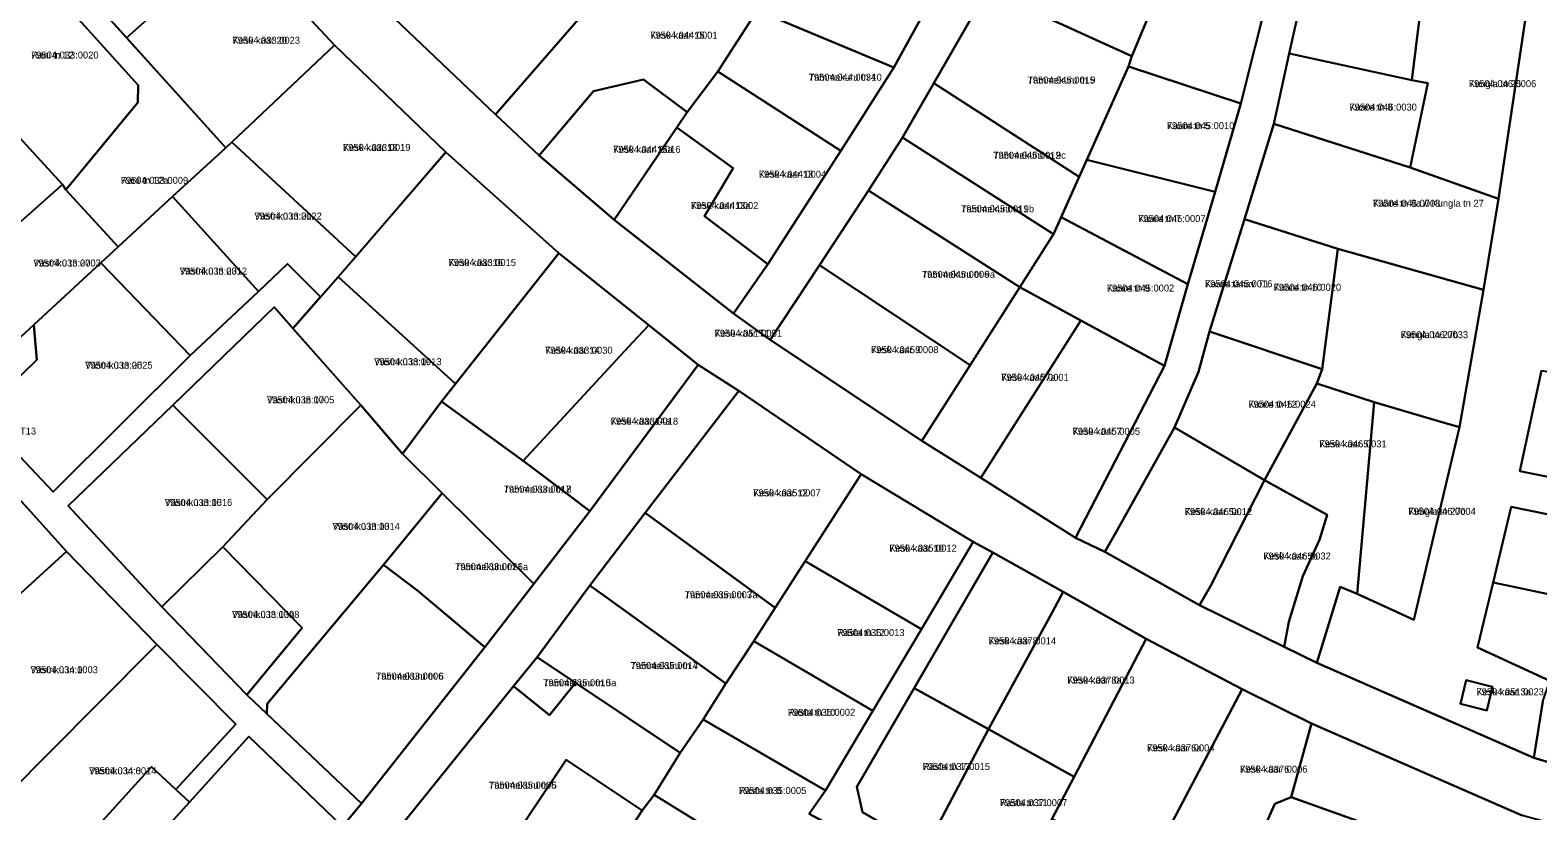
# Model space of a CAD drawing. Extents: x 643847 to 663718, y 6468443 to 6482775.
# Drawn here: x 658477 to 658801.3, y 6472072.8 to 6472240.8 of the extents above; entities that cross this region are included whole.
import ezdxf

# ---------------------------------------------------------------- set-up
doc = ezdxf.new("R2010")
doc.units = 0
for name, color, linetype in [('L_AADRESS', 7, 'Continuous'), ('PIIR', 7, 'Continuous'), ('TUNNUS', 7, 'Continuous')]:
    doc.layers.add(name, color=color, linetype=linetype)

msp = doc.modelspace()

# ---------------------------------------------------------------- linework, layer by layer
at = {"layer": 'PIIR'}
for points in [[(658501.31, 6472282.78), (658521.37, 6472260.27), (658497.7, 6472239.15), (658477.51, 6472261.56)], [(658674.31, 6472253.79), (658662.74, 6472232.74), (658633.36, 6472245.03), (658646.68, 6472277.15), (658679.34, 6472264.45)], [(658553.88, 6472244.64), (658578.06, 6472272.69), (658601.23, 6472250.52), (658577.08, 6472222.66)], [(658691.93, 6472269.29), (658723.96, 6472259.97), (658722.5, 6472256.13), (658721.04, 6472252.31), (658713.91, 6472235.24), (658682.82, 6472249.43)], [(658577.08, 6472222.66), (658601.23, 6472250.52), (658613.02, 6472264.12), (658615.23, 6472261.95), (658617.74, 6472260.17), (658633.36, 6472245.03), (658624.87, 6472231.88), (658618.28, 6472223.16), (658608.9, 6472230.22), (658598.11, 6472227.64), (658586.42, 6472213.82)], [(658477.51, 6472261.56), (658495.65, 6472241.43), (658519.04, 6472215.49), (658507.6, 6472204.98), (658495.9, 6472194.17), (658484.64, 6472206.47), (658500.11, 6472225.22), (658500.19, 6472228.97), (658473.85, 6472258.16)], [(658542.42, 6472237.59), (658520.34, 6472216.73), (658519.04, 6472215.49), (658497.7, 6472239.15), (658521.37, 6472260.27)], [(658473.85, 6472258.16), (658500.19, 6472228.97), (658500.11, 6472225.22), (658484.64, 6472206.47), (658483.9, 6472207.58), (658454.15, 6472239.98)], [(658737.36, 6472225.01), (658713.24, 6472232.98), (658713.91, 6472235.24), (658721.04, 6472252.31), (658722.5, 6472256.13), (658743.33, 6472248.77)], [(658752.03, 6472254.71), (658776.81, 6472251.57), (658774.16, 6472230.07), (658747.8, 6472235.78)], [(658682.82, 6472249.43), (658713.91, 6472235.24), (658713.24, 6472232.98), (658704.23, 6472212.87), (658702.59, 6472209.21), (658671.32, 6472229.38)], [(658773.82, 6472211.22), (658777.6, 6472229.42), (658774.16, 6472230.07), (658776.81, 6472251.57), (658799.04, 6472248.64), (658798.58, 6472243.38), (658792.84, 6472204.51)], [(658633.36, 6472245.03), (658662.74, 6472232.74), (658651.33, 6472214.81), (658624.87, 6472231.88)], [(658454.04, 6472189.46), (658430.48, 6472218.38), (658454.15, 6472239.98), (658483.9, 6472207.58), (658460.17, 6472186.56)], [(658566.41, 6472214.54), (658547, 6472192.05), (658520.34, 6472216.73), (658542.42, 6472237.59)], [(658747.8, 6472235.78), (658774.16, 6472230.07), (658777.6, 6472229.42), (658773.82, 6472211.22), (658744.49, 6472220.66)], [(658731.83, 6472206.01), (658704.23, 6472212.87), (658713.24, 6472232.98), (658737.36, 6472225.01)], [(658586.42, 6472213.82), (658598.11, 6472227.64), (658608.9, 6472230.22), (658618.28, 6472223.16), (658616.05, 6472219.84), (658602.56, 6472199.98)], [(658635.63, 6472190.46), (658622.05, 6472200.8), (658628.21, 6472211.12), (658616.05, 6472219.84), (658618.28, 6472223.16), (658624.87, 6472231.88), (658651.33, 6472214.81)], [(658671.32, 6472229.38), (658702.59, 6472209.21), (658698.72, 6472200.54), (658697.08, 6472196.89), (658664.62, 6472217.69)], [(658602.56, 6472199.98), (658616.05, 6472219.84), (658628.21, 6472211.12), (658622.05, 6472200.8), (658635.63, 6472190.46), (658628.28, 6472179.79)], [(658744.49, 6472220.66), (658773.82, 6472211.22), (658792.84, 6472204.51), (658789.58, 6472184.94), (658758.26, 6472193.72), (658738.2, 6472200.11)], [(658532.31, 6472190.51), (658526.1, 6472184.58), (658507.6, 6472204.98), (658519.04, 6472215.49), (658520.34, 6472216.73), (658547, 6472192.05), (658543.24, 6472187.7), (658539.44, 6472183.38)], [(658664.62, 6472217.69), (658697.08, 6472196.89), (658689.83, 6472185.51), (658657.3, 6472206.3)], [(658590.68, 6472192.79), (658568.44, 6472164.71), (658543.24, 6472187.7), (658566.41, 6472214.54)], [(658725.96, 6472186.14), (658698.72, 6472200.54), (658702.59, 6472209.21), (658704.23, 6472212.87), (658731.83, 6472206.01)], [(658492.15, 6472190.71), (658477.72, 6472177.39), (658472.22, 6472172.3), (658460.17, 6472186.56), (658483.9, 6472207.58), (658484.64, 6472206.47), (658495.9, 6472194.17)], [(658511.35, 6472170.82), (658492.15, 6472190.71), (658495.9, 6472194.17), (658507.6, 6472204.98), (658526.1, 6472184.58)], [(658657.3, 6472206.3), (658689.83, 6472185.51), (658679.13, 6472168.7), (658646.77, 6472190.2)], [(658720.94, 6472168.56), (658702.98, 6472178.34), (658689.83, 6472185.51), (658697.08, 6472196.89), (658698.72, 6472200.54), (658725.96, 6472186.14)], [(658738.2, 6472200.11), (658758.26, 6472193.72), (658754.9, 6472167.83), (658730.65, 6472175.96)], [(658784.45, 6472155.33), (658779.65, 6472156.74), (658766.03, 6472160.72), (658753.73, 6472164.79), (658754.9, 6472167.83), (658758.26, 6472193.72), (658789.58, 6472184.94)], [(658466.22, 6472157.98), (658478.38, 6472169.82), (658477.72, 6472177.39), (658492.15, 6472190.71), (658511.35, 6472170.82), (658481.91, 6472141.41)], [(658590.68, 6472192.79), (658610.02, 6472177.32), (658606.63, 6472173.64), (658583.01, 6472148.14), (658565.46, 6472160.9), (658568.44, 6472164.71)], [(658543.24, 6472187.7), (658568.44, 6472164.71), (658565.46, 6472160.9), (658557.06, 6472149.62), (658548.1, 6472160.09), (658533.49, 6472176.63)], [(658646.77, 6472190.2), (658679.13, 6472168.7), (658668.75, 6472152.39), (658636.16, 6472174.16)], [(658668.75, 6472152.39), (658679.13, 6472168.7), (658689.83, 6472185.51), (658702.98, 6472178.34), (658681.44, 6472144.43)], [(658529.48, 6472181.17), (658548.1, 6472160.09), (658527.94, 6472139.8), (658507.62, 6472160.1)], [(658620.68, 6472168.8), (658597.38, 6472137.31), (658593.39, 6472140.32), (658583.01, 6472148.14), (658606.63, 6472173.64), (658610.02, 6472177.32)], [(658681.44, 6472144.43), (658702.98, 6472178.34), (658720.94, 6472168.56), (658701.84, 6472131.51)], [(658728.29, 6472167.28), (658730.65, 6472175.96), (658754.9, 6472167.83), (658753.73, 6472164.79), (658742.46, 6472143.92), (658723.12, 6472155.28)], [(658486.97, 6471987.22), (658470.14, 6471967.41), (658462.76, 6471973.64), (658481.78, 6471995.53), (658502.37, 6472019.24), (658520.73, 6472040.77), (658544.18, 6472069.39), (658548.25, 6472074.35), (658574.77, 6472108.01), (658585.28, 6472121.63), (658597.38, 6472137.31), (658620.68, 6472168.8), (658629.38, 6472163.16), (658609.28, 6472136.89), (658597.33, 6472121.3), (658586.04, 6472105.83), (658580.96, 6472099.65), (658555.3, 6472067.81), (658551.14, 6472062.72), (658529, 6472036.46), (658513.76, 6472018.4), (658509.71, 6472013.53)], [(658802.08, 6472167.57), (658837.99, 6472160.95), (658835.29, 6472143.37), (658834.56, 6472138.45), (658797.4, 6472145.92)], [(658746.72, 6472108.09), (658747.7, 6472113.44), (658750.72, 6472123.27), (658754.32, 6472131.14), (658755.93, 6472136.48), (658742.46, 6472143.92), (658753.73, 6472164.79), (658766.03, 6472160.72), (658762.37, 6472119.49), (658758.74, 6472120.97), (658755.74, 6472111.16), (658753.71, 6472104.63)], [(658655.71, 6472145.26), (658643.66, 6472126.52), (658637.19, 6472116.45), (658609.28, 6472136.89), (658629.38, 6472163.16)], [(658527.94, 6472139.8), (658518.41, 6472129.58), (658505.27, 6472116.72), (658485.17, 6472138.46), (658507.62, 6472160.1)], [(658523.57, 6472097.77), (658535.49, 6472112.17), (658518.41, 6472129.58), (658527.94, 6472139.8), (658548.1, 6472160.09), (658557.06, 6472149.62), (658565.58, 6472141.17), (658552.94, 6472125.71), (658527.97, 6472095.81), (658527.89, 6472093.66)], [(658585.28, 6472121.63), (658565.58, 6472141.17), (658557.06, 6472149.62), (658565.46, 6472160.9), (658583.01, 6472148.14), (658593.39, 6472140.32), (658597.38, 6472137.31)], [(658774.61, 6472113.89), (658770.07, 6472115.97), (658762.37, 6472119.49), (658766.03, 6472160.72), (658779.65, 6472156.74), (658784.45, 6472155.33)], [(658708.16, 6472128.51), (658710.69, 6472133.05), (658723.12, 6472155.28), (658742.46, 6472143.92), (658730.95, 6472121.26), (658728.52, 6472117.08)], [(658451.55, 6472144.62), (658455.66, 6472140.04), (658466.05, 6472149.31), (658484.75, 6472128.6), (658455.79, 6472102.23), (658433.63, 6472128.35)], [(658679.82, 6472130.67), (658668.68, 6472111.88), (658643.66, 6472126.52), (658655.71, 6472145.26)], [(658728.52, 6472117.08), (658730.95, 6472121.26), (658742.46, 6472143.92), (658755.93, 6472136.48), (658754.32, 6472131.14), (658750.72, 6472123.27), (658747.7, 6472113.44), (658746.72, 6472108.09)], [(658574.77, 6472108.01), (658560.33, 6472120.14), (658552.94, 6472125.71), (658565.58, 6472141.17), (658585.28, 6472121.63)], [(658609.28, 6472136.89), (658637.19, 6472116.45), (658632.6, 6472109.31), (658626.6, 6472100.21), (658601.39, 6472118.38), (658597.33, 6472121.3)], [(658795.56, 6472138.2), (658833.2, 6472130.55), (658832.6, 6472126.98), (658830.37, 6472113.72), (658791.67, 6472121.95)], [(658505.27, 6472116.72), (658518.41, 6472129.58), (658535.49, 6472112.17), (658523.57, 6472097.77)], [(658670.36, 6472019.49), (658658.46, 6471997.89), (658653.44, 6472001.73), (658672.58, 6472036.92), (658678.34, 6472047.5), (658676.34, 6472053.77), (658649.48, 6472069.46), (658644.52, 6472072.15), (658648.05, 6472077.18), (658658.22, 6472094.28), (658668.68, 6472111.88), (658679.82, 6472130.67), (658684.01, 6472128.39), (658667.09, 6472099.2), (658654.75, 6472077.92), (658656.02, 6472072.5), (658669.53, 6472064.64), (658681.97, 6472057.51), (658691.21, 6472060.31), (658688.96, 6472054.5), (658679.74, 6472037.54)], [(658487.19, 6472126.08), (658504.19, 6472108.57), (658491.16, 6472095.44), (658472.1, 6472076.22), (658452.09, 6472098.87), (658455.79, 6472102.23), (658484.75, 6472128.6)], [(658548.25, 6472074.35), (658527.89, 6472093.66), (658527.97, 6472095.81), (658552.94, 6472125.71), (658560.33, 6472120.14), (658574.77, 6472108.01)], [(658658.22, 6472094.28), (658632.6, 6472109.31), (658637.19, 6472116.45), (658643.66, 6472126.52), (658668.68, 6472111.88)], [(658684.01, 6472128.39), (658699.19, 6472119.89), (658696.8, 6472115.5), (658683.12, 6472090.34), (658667.09, 6472099.2)], [(658597.33, 6472121.3), (658601.39, 6472118.38), (658626.6, 6472100.21), (658621.75, 6472092.42), (658616.79, 6472085.28), (658594.25, 6472100.36), (658586.04, 6472105.83)], [(658716.99, 6472109.8), (658701.56, 6472080.14), (658683.12, 6472090.34), (658696.8, 6472115.5), (658699.19, 6472119.89)], [(658853.88, 6472071.07), (658834.71, 6472075.16), (658815.16, 6472079.85), (658800.44, 6472084.23), (658802.33, 6472096.34), (658803.83, 6472100.78), (658788.31, 6472107.93), (658791.67, 6472121.95), (658830.37, 6472113.72), (658827.65, 6472097.48), (658846.62, 6472093.3), (658856.41, 6472091.14), (658865.05, 6472090.8), (658861.31, 6472069.89)], [(658648.05, 6472077.18), (658621.75, 6472092.42), (658626.6, 6472100.21), (658632.6, 6472109.31), (658658.22, 6472094.28)], [(658737.66, 6472098.99), (658721.87, 6472068.98), (658718.03, 6472061.11), (658696.76, 6472071.01), (658701.56, 6472080.14), (658716.99, 6472109.8)], [(658521.24, 6472091.45), (658508.32, 6472077.4), (658503.09, 6472082.27), (658472.25, 6472048.25), (658458.02, 6472062.02), (658472.1, 6472076.22), (658491.16, 6472095.44), (658504.19, 6472108.57)], [(658586.04, 6472105.83), (658594.25, 6472100.36), (658588.71, 6472093.38), (658580.96, 6472099.65)], [(658580.96, 6472099.65), (658588.71, 6472093.38), (658594.25, 6472100.36), (658616.79, 6472085.28), (658611.19, 6472076.22), (658608.6, 6472072.86), (658592.28, 6472083.8), (658575.79, 6472059.09), (658572.96, 6472054.74), (658555.3, 6472067.81)], [(658784.65, 6472095.85), (658785.86, 6472100.93), (658791.49, 6472099.44), (658790.28, 6472094.36)], [(658790.28, 6472094.36), (658791.49, 6472099.44), (658785.86, 6472100.93), (658784.65, 6472095.85)], [(658667.09, 6472099.2), (658683.12, 6472090.34), (658669.53, 6472064.64), (658656.02, 6472072.5), (658654.75, 6472077.92)], [(658752.56, 6472091.57), (658748.23, 6472075.76), (658744.7, 6472074.32), (658739.68, 6472063.05), (658721.87, 6472068.98), (658737.66, 6472098.99)], [(658649.48, 6472069.46), (658643.98, 6472060.39), (658627.69, 6472070.13), (658625.82, 6472067.19), (658611.19, 6472076.22), (658616.79, 6472085.28), (658621.75, 6472092.42), (658648.05, 6472077.18), (658644.52, 6472072.15)], [(658683.12, 6472090.34), (658701.56, 6472080.14), (658696.76, 6472071.01), (658691.21, 6472060.31), (658681.97, 6472057.51), (658669.53, 6472064.64)], [(658520.73, 6472040.77), (658497.89, 6472059.97), (658511.24, 6472074.68), (658524.02, 6472088.79), (658544.18, 6472069.39)], [(658589.6, 6472043.55), (658572.96, 6472054.74), (658575.79, 6472059.09), (658592.28, 6472083.8), (658608.6, 6472072.86), (658592.28, 6472047.69)], [(658497.89, 6472059.97), (658480.25, 6472040.51), (658472.25, 6472048.25), (658503.09, 6472082.27), (658508.32, 6472077.4), (658511.24, 6472074.68)], [(658589.6, 6472043.55), (658592.28, 6472047.69), (658608.6, 6472072.86), (658611.19, 6472076.22), (658625.82, 6472067.19), (658604.12, 6472033.8)], [(658753.94, 6472045.33), (658718.7, 6472060.93), (658718.03, 6472061.11), (658721.87, 6472068.98), (658739.68, 6472063.05), (658744.7, 6472074.32), (658748.23, 6472075.76), (658762.23, 6472070.73)]]:
    msp.add_lwpolyline(points, close=True, dxfattribs=at)
for points in [[(658832.21, 6472062.37), (658797.91, 6472071.79), (658752.56, 6472091.57), (658737.66, 6472098.99), (658716.99, 6472109.8), (658699.19, 6472119.89), (658684.01, 6472128.39), (658679.82, 6472130.67), (658655.71, 6472145.26), (658629.38, 6472163.16), (658620.68, 6472168.8), (658610.02, 6472177.32), (658590.68, 6472192.79), (658566.41, 6472214.54), (658542.42, 6472237.59), (658521.37, 6472260.27)], [(658682.82, 6472249.43), (658671.32, 6472229.38), (658664.62, 6472217.69), (658657.3, 6472206.3), (658646.77, 6472190.2), (658636.16, 6472174.16), (658628.28, 6472179.79), (658635.63, 6472190.46), (658651.33, 6472214.81), (658662.74, 6472232.74), (658674.31, 6472253.79)], [(658752.03, 6472254.71), (658747.8, 6472235.78), (658744.49, 6472220.66), (658738.2, 6472200.11), (658730.65, 6472175.96), (658728.29, 6472167.28), (658723.12, 6472155.28), (658710.69, 6472133.05), (658708.16, 6472128.51), (658701.84, 6472131.51), (658720.94, 6472168.56), (658725.96, 6472186.14), (658731.83, 6472206.01), (658737.36, 6472225.01), (658743.33, 6472248.77)], [(658553.88, 6472244.64), (658577.08, 6472222.66), (658586.42, 6472213.82), (658602.56, 6472199.98), (658628.28, 6472179.79), (658636.16, 6472174.16), (658668.75, 6472152.39), (658681.44, 6472144.43), (658701.84, 6472131.51), (658708.16, 6472128.51), (658728.52, 6472117.08), (658746.72, 6472108.09), (658753.71, 6472104.63), (658800.44, 6472084.23), (658815.16, 6472079.85)], [(658802.33, 6472096.34), (658800.44, 6472084.23), (658753.71, 6472104.63), (658755.74, 6472111.16), (658758.74, 6472120.97), (658762.37, 6472119.49), (658770.07, 6472115.97), (658774.61, 6472113.89), (658784.45, 6472155.33), (658789.58, 6472184.94), (658792.84, 6472204.51), (658798.58, 6472243.38)], [(658472.22, 6472172.3), (658477.72, 6472177.39), (658478.38, 6472169.82), (658466.22, 6472157.98), (658481.91, 6472141.41), (658511.35, 6472170.82), (658526.1, 6472184.58), (658532.31, 6472190.51), (658539.44, 6472183.38), (658533.49, 6472176.63), (658529.48, 6472181.17), (658507.62, 6472160.1), (658485.17, 6472138.46), (658505.27, 6472116.72), (658523.57, 6472097.77), (658527.89, 6472093.66), (658548.25, 6472074.35), (658544.18, 6472069.39), (658524.02, 6472088.79), (658511.24, 6472074.68), (658508.32, 6472077.4), (658521.24, 6472091.45), (658504.19, 6472108.57), (658487.19, 6472126.08), (658484.75, 6472128.6), (658466.05, 6472149.31)], [(658802.08, 6472167.57), (658797.4, 6472145.92), (658834.56, 6472138.45)], [(658833.2, 6472130.55), (658795.56, 6472138.2), (658791.67, 6472121.95), (658788.31, 6472107.93), (658803.83, 6472100.78)], [(658762.23, 6472070.73), (658748.23, 6472075.76), (658752.56, 6472091.57), (658797.91, 6472071.79)]]:
    msp.add_lwpolyline(points, dxfattribs=at)

# ---------------------------------------------------------------- texts
at = {"layer": 'L_AADRESS'}
for s, p in [('Kesk kaar 20', (658520.5, 6472237.88)), ('Kesk kaar 15', (658610.33, 6472238.97)), ('Räni tn 12', (658477.17, 6472234.7)), ('Tammekuru tn 10', (658644.43, 6472229.92)), ('Tammekuru tn 9', (658691.51, 6472229.32)), ('Kungla tn 25', (658786.43, 6472228.54)), ('Kaare tn 8', (658760.74, 6472223.5)), ('Kaare tn 5', (658721.48, 6472219.5)), ('Kesk kaar 18', (658544.26, 6472214.82)), ('Kesk kaar 15a', (658602.35, 6472214.41)), ('Tammekuru tn 9c', (658684.12, 6472213.13)), ('Kesk kaar 13', (658633.69, 6472209.06)), ('Räni tn 12a', (658496.45, 6472207.73)), ('Kesk kaar 13a', (658619.1, 6472202.33)), ('Kaare tn 8a // Kungla tn 27', (658765.79, 6472202.8)), ('Västriku tn 21', (658525.21, 6472200.05)), ('Tammekuru tn 9b', (658677.19, 6472201.6)), ('Kaare tn 7', (658715.29, 6472199.51)), ('Västriku tn 27', (658477.65, 6472189.94)), ('Kesk kaar 16', (658566.96, 6472190.05)), ('Västriku tn 23', (658509.12, 6472188.21)), ('Tammekuru tn 9a', (658668.78, 6472187.5)), ('Kaare tn 9', (658708.55, 6472184.55)), ('Kaare tänav T1', (658729.66, 6472185.47)), ('Kaare tn 10', (658744.45, 6472184.72)), ('Kesk kaar T1', (658624.19, 6472174.82)), ('Kungla tn 27b', (658771.77, 6472174.52)), ('Kesk kaar 14', (658587.74, 6472171.16)), ('Kesk kaar 9', (658657.84, 6472171.29)), ('Västriku tn 25', (658488.79, 6472167.94)), ('Västriku tn 19', (658550.96, 6472168.7)), ('Kesk kaar 7a', (658685.86, 6472165.34)), ('Västriku tn 17', (658527.89, 6472160.49)), ('Kaare tn 12', (658739.01, 6472159.55)), ('Västriku tänav T13', (658461.52, 6472153.77)), ('Kesk kaar 14a', (658601.84, 6472155.91)), ('Kesk kaar 7', (658701.19, 6472153.72)), ('Kesk kaar 5', (658754.25, 6472151.02)), ('Tammekuru tn 8', (658578.81, 6472141.26)), ('Kesk kaar 12', (658632.5, 6472140.47)), ('Västriku tn 15', (658505.93, 6472138.41)), ('Kesk kaar 5a', (658725.31, 6472136.44)), ('Kungla tn 27c', (658773.41, 6472136.5)), ('Västriku tn 13', (658541.99, 6472133.27)), ('Kesk kaar 10', (658661.78, 6472128.57)), ('Tammekuru tn 6a', (658568.36, 6472124.59)), ('Kesk kaar 5b', (658742.23, 6472126.88)), ('Tammekuru tn 7a', (658617.74, 6472118.55)), ('Västriku tn 13a', (658520.38, 6472114.32)), ('Rästa tn 12', (658650.55, 6472110.4)), ('Kesk kaar 8', (658683.14, 6472108.63)), ('Västriku tn 10', (658477.03, 6472102.41)), ('Tammekuru tn 7', (658606.09, 6472103.29)), ('Tammekuru tn 6', (658551.33, 6472101.02)), ('Tammekuru tn 5a', (658587.33, 6472099.6)), ('Kesk kaar 8a', (658700.05, 6472100.19)), ('Kesk kaar 3a', (658788.07, 6472097.65)), ('Rästa tn 10', (658639.93, 6472093.24)), ('Kesk kaar 6a', (658717.21, 6472085.59)), ('Västriku tn 8', (658489.63, 6472080.66)), ('Rästa tn 13', (658668.93, 6472081.58)), ('Kesk kaar 6', (658737.21, 6472081.01)), ('Tammekuru tn 5', (658575.63, 6472077.55)), ('Rästa tn 8', (658629.41, 6472076.41)), ('Rästa tn 11', (658685.55, 6472073.8))]:
    msp.add_text(s, height=1.5, dxfattribs=at).set_placement(p)
at = {"layer": 'TUNNUS'}
for s, p in [('79504:033:0023', (658520.5, 6472237.88)), ('79504:044:0001', (658610.33, 6472238.97)), ('79504:033:0020', (658477.17, 6472234.7)), ('79504:044:0034', (658644.43, 6472229.92)), ('79504:045:0015', (658691.51, 6472229.32)), ('79504:046:0006', (658786.43, 6472228.54)), ('79504:046:0030', (658760.74, 6472223.5)), ('79504:045:0010', (658721.48, 6472219.5)), ('79504:033:0019', (658544.26, 6472214.82)), ('79504:044:0016', (658602.35, 6472214.41)), ('79504:045:0012', (658684.12, 6472213.13)), ('79504:044:0004', (658633.69, 6472209.06)), ('79504:033:0009', (658496.45, 6472207.73)), ('79504:044:0002', (658619.1, 6472202.33)), ('79504:046:0008', (658765.79, 6472202.8)), ('79504:033:0022', (658525.21, 6472200.05)), ('79504:045:0011', (658677.19, 6472201.6)), ('79504:045:0007', (658715.29, 6472199.51)), ('79504:033:0003', (658477.65, 6472189.94)), ('79504:033:0015', (658566.96, 6472190.05)), ('79504:033:0012', (658509.12, 6472188.21)), ('79504:045:0006', (658668.78, 6472187.5)), ('79504:045:0002', (658708.55, 6472184.55)), ('79504:045:0016', (658729.66, 6472185.47)), ('79504:046:0020', (658744.45, 6472184.72)), ('79504:051:0051', (658624.19, 6472174.82)), ('79504:046:0033', (658771.77, 6472174.52)), ('79504:033:0030', (658587.74, 6472171.16)), ('79504:045:0008', (658657.84, 6472171.29)), ('79504:033:0025', (658488.79, 6472167.94)), ('79504:033:0013', (658550.96, 6472168.7)), ('79504:045:0001', (658685.86, 6472165.34)), ('79504:033:0005', (658527.89, 6472160.49)), ('79504:046:0024', (658739.01, 6472159.55)), ('79504:033:0018', (658601.84, 6472155.91)), ('79504:045:0005', (658701.19, 6472153.72)), ('79504:046:0031', (658754.25, 6472151.02)), ('79504:033:0017', (658578.81, 6472141.26)), ('79504:035:0007', (658632.5, 6472140.47)), ('79504:033:0016', (658505.93, 6472138.41)), ('79504:046:0012', (658725.31, 6472136.44)), ('79504:046:0004', (658773.41, 6472136.5)), ('79504:033:0014', (658541.99, 6472133.27)), ('79504:035:0012', (658661.78, 6472128.57)), ('79504:033:0021', (658568.36, 6472124.59)), ('79504:046:0032', (658742.23, 6472126.88)), ('79504:035:0003', (658617.74, 6472118.55)), ('79504:033:0008', (658520.38, 6472114.32)), ('79504:035:0013', (658650.55, 6472110.4)), ('79504:037:0014', (658683.14, 6472108.63)), ('79504:034:0003', (658477.03, 6472102.41)), ('79504:035:0014', (658606.09, 6472103.29)), ('79504:033:0006', (658551.33, 6472101.02)), ('79504:035:0010', (658587.33, 6472099.6)), ('79504:037:0013', (658700.05, 6472100.19)), ('79504:051:0023', (658788.07, 6472097.65)), ('79504:035:0002', (658639.93, 6472093.24)), ('79504:037:0004', (658717.21, 6472085.59)), ('79504:034:0014', (658489.63, 6472080.66)), ('79504:037:0015', (658668.93, 6472081.58)), ('79504:037:0006', (658737.21, 6472081.01)), ('79504:035:0006', (658575.63, 6472077.55)), ('79504:035:0005', (658629.41, 6472076.41)), ('79504:037:0007', (658685.55, 6472073.8))]:
    msp.add_text(s, height=1.5, dxfattribs=at).set_placement(p)

doc.saveas('drawing.dxf')
